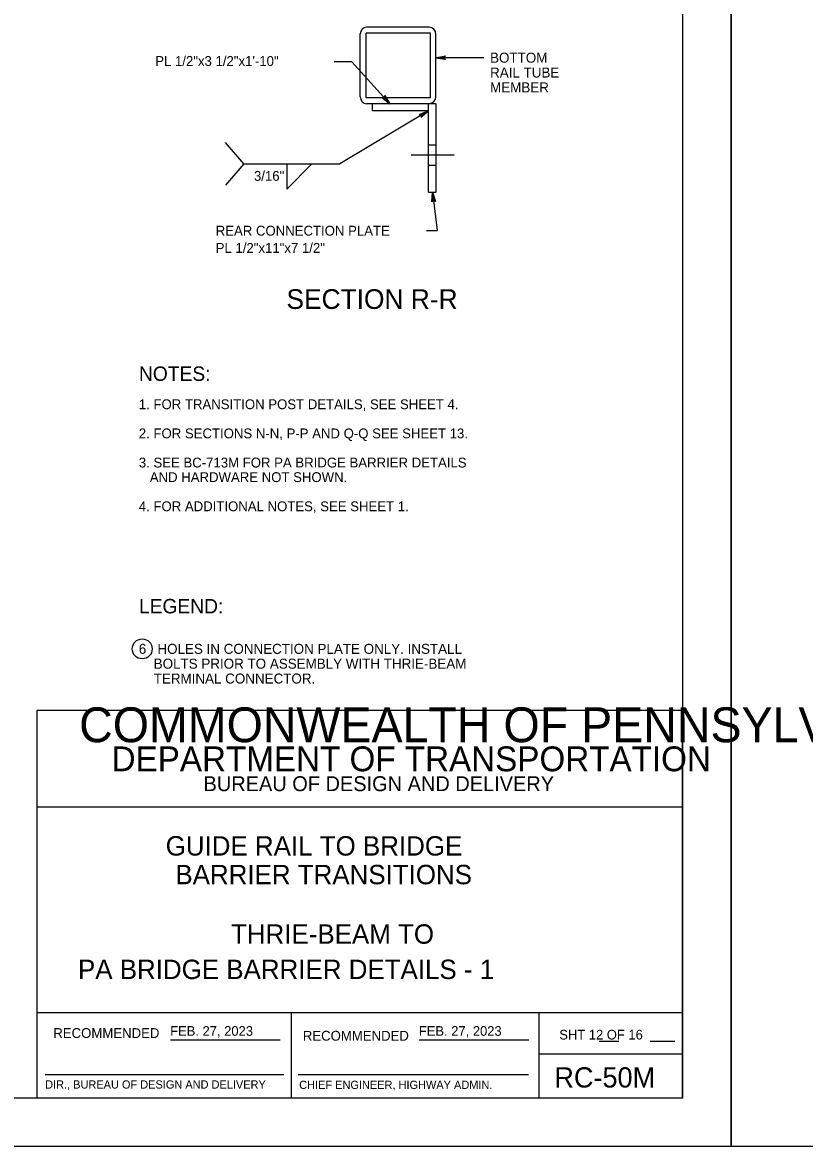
# Model space of a CAD drawing. Extents: x 632007860 to 635435983, y 295418622 to 297794622.
# Drawn here: x 634311463 to 634553598, y 295418622 to 295766521 of the extents above; entities that cross this region are included whole.
import ezdxf

# ---------------------------------------------------------------- set-up
doc = ezdxf.new("R2010")
doc.units = 0
for name, color, linetype in [('1', 7, 'Continuous'), ('2', 7, 'Continuous'), ('8', 7, 'Continuous'), ('PLT-BNDY', 7, 'Continuous'), ('S-DETL-DIMS', 7, 'Continuous'), ('S-DETL-T120', 7, 'Continuous'), ('S-DETL-T175', 7, 'Continuous'), ('S-DETL-T240', 7, 'Continuous'), ('S-MISC-CNTR-WT01', 7, 'Continuous'), ('S-STEL', 7, 'Continuous')]:
    doc.layers.add(name, color=color, linetype=linetype)

msp = doc.modelspace()

# ---------------------------------------------------------------- linework, layer by layer
at = {"layer": '1'}
for p, q in [((634515860, 295997622), (634515860, 295433622)), ((634515860, 295553622), (634315860, 295553622)), ((634315860, 295553622), (634315860, 295433622)), ((634515860, 295433622), (634515860, 295553622)), ((634515860, 295523622), (634315860, 295523622)), ((634515860, 295459981), (634315860, 295459981)), ((634394661, 295459981), (634394661, 295433622)), ((634471362, 295459981), (634471362, 295433622)), ((634357325, 295451611), (634391211, 295451611)), ((634434323, 295451611), (634468193, 295451611)), ((634489995, 295451243), (634496137, 295451243)), ((634505756, 295451243), (634513402, 295451243)), ((634471362, 295447300), (634515860, 295447300)), ((634318485, 295440918), (634392385, 295440918)), ((634396791, 295440918), (634468131, 295440918)), ((634515860, 295433622), (633729860, 295433622))]:
    msp.add_line(p, q, dxfattribs=at)
at = {"layer": '8'}
msp.add_line((634445151, 295725402), (634431837, 295725402), dxfattribs=at)
at = {"layer": 'PLT-BNDY'}
for points in [[(633689860, 296012622), (634530860, 296012622), (634530860, 295418622), (633689860, 295418622)], [(634530860, 296012622), (635371860, 296012622), (635371860, 295418622), (634530860, 295418622)]]:
    msp.add_lwpolyline(points, close=True, dxfattribs=at)
at = {"layer": 'S-DETL-DIMS'}
for p, q in [((634454294, 295755604), (634439477, 295755604)), ((634413428, 295754305), (634407943, 295754305)), ((634425219, 295741389), (634413428, 295754305)), ((634437179, 295739124), (634409704, 295722806)), ((634379962, 295722806), (634374296, 295729412)), ((634379962, 295722806), (634374296, 295716198)), ((634379962, 295722806), (634409704, 295722806)), ((634393340, 295714940), (634401049, 295722806)), ((634393340, 295722806), (634393340, 295714940)), ((634438415, 295713966), (634439899, 295702120)), ((634436587, 295702120), (634439899, 295702120))]:
    msp.add_line(p, q, dxfattribs=at)
for points in [[(634439477, 295755604), (634442437, 295756159), (634442323, 295756080), (634442209, 295756001), (634442150, 295755901), (634442091, 295755802), (634442074, 295755703), (634442057, 295755604), (634442074, 295755505), (634442091, 295755405), (634442150, 295755306), (634442209, 295755207), (634442323, 295755128), (634442437, 295755049), (634439477, 295755604), (634442323, 295755128), (634442209, 295755207), (634439477, 295755604), (634442150, 295755306), (634442091, 295755405), (634439477, 295755604), (634442074, 295755505), (634442057, 295755604), (634439477, 295755604), (634442074, 295755703), (634442091, 295755802), (634439477, 295755604), (634442150, 295755901), (634442209, 295756001), (634439477, 295755604), (634442323, 295756080)], [(634425219, 295741389), (634422814, 295743200), (634422949, 295743169), (634423084, 295743138), (634423197, 295743162), (634423310, 295743185), (634423395, 295743240), (634423480, 295743294), (634423542, 295743373), (634423603, 295743453), (634423637, 295743563), (634423671, 295743674), (634423652, 295743811), (634423634, 295743948), (634425219, 295741389), (634423652, 295743811), (634423671, 295743674), (634425219, 295741389), (634423637, 295743563), (634423603, 295743453), (634425219, 295741389), (634423542, 295743373), (634423480, 295743294), (634425219, 295741389), (634423395, 295743240), (634423310, 295743185), (634425219, 295741389), (634423197, 295743162), (634423084, 295743138), (634425219, 295741389), (634422949, 295743169)], [(634437179, 295739124), (634434918, 295737136), (634434975, 295737262), (634435033, 295737388), (634435033, 295737503), (634435033, 295737619), (634434997, 295737713), (634434961, 295737807), (634434895, 295737883), (634434830, 295737960), (634434729, 295738015), (634434628, 295738071), (634434489, 295738080), (634434351, 295738090), (634437179, 295739124), (634434489, 295738080), (634434628, 295738071), (634437179, 295739124), (634434729, 295738015), (634434830, 295737960), (634437179, 295739124), (634434895, 295737883), (634434961, 295737807), (634437179, 295739124), (634434997, 295737713), (634435033, 295737619), (634437179, 295739124), (634435033, 295737503), (634435033, 295737388), (634437179, 295739124), (634434975, 295737262)], [(634438415, 295713966), (634439334, 295711098), (634439241, 295711202), (634439149, 295711305), (634439043, 295711351), (634438937, 295711397), (634438837, 295711402), (634438736, 295711406), (634438640, 295711377), (634438543, 295711348), (634438452, 295711277), (634438361, 295711206), (634438297, 295711084), (634438233, 295710961), (634438415, 295713966), (634438297, 295711084), (634438361, 295711206), (634438415, 295713966), (634438452, 295711277), (634438543, 295711348), (634438415, 295713966), (634438640, 295711377), (634438736, 295711406), (634438415, 295713966), (634438837, 295711402), (634438937, 295711397), (634438415, 295713966), (634439043, 295711351), (634439149, 295711305), (634438415, 295713966), (634439241, 295711202)]]:
    msp.add_lwpolyline(points, dxfattribs=at)
at = {"layer": 'S-DETL-T120'}
msp.add_circle((634348530, 295572640), 3081, dxfattribs=at)
at = {"layer": 'S-MISC-CNTR-WT01'}
for p, q in [((634439477, 295728583), (634437179, 295728583)), ((634439477, 295722221), (634437179, 295722221))]:
    msp.add_line(p, q, dxfattribs=at)
at = {"layer": 'S-STEL'}
for p, q in [((634416019, 295743457), (634416019, 295762960)), ((634417872, 295743198), (634417872, 295763219)), ((634437821, 295763219), (634417872, 295763219)), ((634437274, 295765028), (634418087, 295765028)), ((634437821, 295743198), (634437821, 295763219)), ((634439477, 295743415), (634439477, 295762960)), ((634437821, 295743198), (634417872, 295743198)), ((634437274, 295741389), (634418087, 295741389)), ((634419882, 295739124), (634419882, 295741389)), ((634439477, 295741389), (634419882, 295741389)), ((634439477, 295741389), (634419882, 295741389)), ((634437179, 295739124), (634419882, 295739124)), ((634437179, 295713966), (634437179, 295741389)), ((634439477, 295741389), (634439477, 295713966)), ((634437179, 295713966), (634439477, 295713966))]:
    msp.add_line(p, q, dxfattribs=at)
for centre, start, end in [((634418087, 295762960), 90, 180), ((634437409, 295762960), 0, 90), ((634418087, 295743457), 180, 270), ((634437408, 295743510), 270, 0)]:
    msp.add_arc(centre, 2068, start, end, dxfattribs=at)

# ---------------------------------------------------------------- texts
at = {"layer": '1'}
for s, height, p in [('COMMONWEALTH OF PENNSYLVANIA', 10783.37, (634329011, 295543766)), ('DEPARTMENT OF TRANSPORTATION', 7684.29, (634339072, 295534771)), ('BUREAU OF DESIGN AND DELIVERY', 4622.09, (634367520, 295528609)), ('RECOMMENDED', 3048, (634321023, 295452216)), ('FEB. 27, 2023', 3000, (634357186, 295452887)), ('RECOMMENDED', 3048, (634398267, 295451379)), ('FEB. 27, 2023', 3000, (634434184, 295452887)), ('SHT 12 OF 16', 3000, (634477666, 295451742)), ('APPROVED', 19.2, (634358883, 295451554)), ('RC-50M', 6267.5, (634476143, 295436882)), ('DIR., BUREAU OF DESIGN AND DELIVERY', 2540, (634318485, 295436554)), ('CHIEF ENGINEER, HIGHWAY ADMIN.', 2540, (634397144, 295436445))]:
    msp.add_text(s, height=height, dxfattribs=at).set_placement(p)
at = {"layer": '2'}
for s, p in [('GUIDE RAIL TO BRIDGE', (634355804, 295508672)), ('BARRIER TRANSITIONS', (634358804, 295499797)), ('THRIE-BEAM TO', (634376032, 295481389)), ('PA BRIDGE BARRIER DETAILS - 1', (634328647, 295470453))]:
    msp.add_text(s, height=6000, dxfattribs=at).set_placement(p)
at = {"layer": 'S-DETL-T120'}
for s, height, p in [('PL 1/2"x3 1/2"x1\'-10"', 3048.01, (634352567, 295753070)), ('BOTTOM', 3102.2, (634456240, 295754071)), ('RAIL TUBE', 3102.2, (634456240, 295749478)), ('MEMBER', 3102.2, (634456240, 295744886)), ('3/16"', 3048, (634383137, 295717516)), ('REAR CONNECTION PLATE', 3048.01, (634371300, 295700552)), ('PL 1/2"x11"x7 1/2"', 3048.01, (634371300, 295695218)), ('6   HOLES IN CONNECTION PLATE ONLY. INSTALL ', 3102.3, (634347487, 295571103)), ('    BOLTS PRIOR TO ASSEMBLY WITH THRIE-BEAM ', 3102.3, (634347487, 295566511)), ('    TERMINAL CONNECTOR.', 3102.3, (634347487, 295561918))]:
    msp.add_text(s, height=height, dxfattribs=at).set_placement(p)
for s, p in [('1. FOR TRANSITION POST DETAILS, SEE SHEET 4.', (634347487, 295646836)), ('2. FOR SECTIONS N-N, P-P AND Q-Q SEE SHEET 13.', (634347487, 295637812)), ('3. SEE BC-713M FOR PA BRIDGE BARRIER DETAILS', (634347487, 295628787)), ('   AND HARDWARE NOT SHOWN.', (634347487, 295624275)), ('4. FOR ADDITIONAL NOTES, SEE SHEET 1.', (634347487, 295615251))]:
    msp.add_text(s, height=3048.06, rotation=360, dxfattribs=at).set_placement(p)
at = {"layer": 'S-DETL-T175'}
for s, p in [('NOTES:', (634347529, 295655600)), ('LEGEND:', (634347529, 295583643))]:
    msp.add_text(s, height=4450, dxfattribs=at).set_placement(p)
at = {"layer": 'S-DETL-T240'}
msp.add_text('SECTION R-R', height=6096, dxfattribs=at).set_placement((634393199, 295677866))

doc.saveas('drawing.dxf')
